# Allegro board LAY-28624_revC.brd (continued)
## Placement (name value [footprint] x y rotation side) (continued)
J56  JT4-1108HL  [CON_RJ45_XG_1X1_LED]  242.32 -1.52 0 top
J57  JMP1  [JMP_P254_T_1X1]  38.35 46.48 0 top
J58  CON_3PIN  [CON_WAFER_P254_S_1X3]  256.92 76.45 0 top
J59  CON_3PIN  [CON_WAFER_P254_S_1X3]  232.16 76.45 0 top
J60  HDR_1X3  [HDR_P254_M_T_1X3]  168.02 66.42 0 top
J61  JMP2  [JMP_P254_T_1X2]  55.88 90.68 0 top
L1  90ohm  [IND_CM_2012]  113.79 28.83 270 bottom
L2  90ohm  [IND_CM_2012]  116.33 28.83 270 bottom
L3  2.2uH  [IND_SWPA2520]  152.91 46.1 180 top
L4  2.2uH  [IND_SWPA2520]  130.68 46.74 180 top
L16  22uH  [IND_45X40]  59.69 130.43 90 top
L17  2.2uH  [IND_IHLP_2525]  189.61 78.23 180 top
L18  2.2uH  [IND_IHLP_2525]  209.93 136.91 180 top
L19  3.3uH  [IND_IHLP_2525]  31.5 112.14 0 top
L20  3.3uH  [IND_IHLP_2525]  31.5 101.35 0 top
L21  4.7uH  [IND_IHLP_2525]  68.96 80.39 0 top
L22  2.2uH  [IND_IHLP_2525]  31.5 90.55 0 top
L23  1.0uH  [IND_IHLP_4040]  115.95 104.52 0 top
L24  2.2uH  [IND_IHLP_2525]  210.19 53.21 270 top
L25  4.7uH  [IND_IHLP_2525]  263.14 53.21 270 top
M3  MH  [MH_580S340P]  261 189.58 180 top
M4  MH  [MH_580S340P]  237.18 189.58 0 top
M5  MH  [MH_580S340P]  261 213.78 180 top
M6  MH  [MH_580S340P]  237.18 213.78 0 top
M7  MH  [MH_580S340P]  207.8 189.58 180 top
M8  MH  [MH_580S340P]  231.95 189.58 180 top
M9  MH  [MH_580S340P]  231.95 213.78 180 top
M10  MH  [MH_580S340P]  207.8 213.78 180 top
M11  MH  [MH_580S340P]  31.56 189.58 0 top
M12  MH  [MH_580S340P]  31.56 213.78 0 top
M13  MH  [MH_580S340P]  7.74 189.58 0 top
M14  MH  [MH_580S340P]  7.74 213.78 0 top
M15  MH  [MH_580S340P]  36.79 189.58 0 top
M16  MH  [MH_580S340P]  36.79 213.78 0 top
M17  MH  [MH_580S340P]  60.94 189.58 0 top
M18  MH  [MH_580S340P]  60.94 213.78 0 top
NOREF  val  [unnamed]  166.12 114.05 90 top
NOREF#2  -  [#2]  -252.98 -202.18 0 top
Q1  IRLML6346  [SOT23]  169.29 91.69 90 bottom
Q2  IRLML6346  [SOT23]  165.23 91.69 270 bottom
Q3  IRLML6346  [SOT23]  102.36 35.94 90 top
Q4  IRLML6346  [SOT23]  97.66 35.94 90 top
Q11  IRFHM4226  [U8_FL]  37.97 99.82 90 top
Q12  IRF9321  [SO_8]  24.51 75.31 0 top
Q15  IRLML6346  [SOT23]  38.35 104.01 180 top
Q16  IRLML6346  [SOT23]  19.05 70.87 0 top
Q17  IRFHM4226  [U8_FL]  75.44 78.87 90 top
Q18  IRFH6200  [SO_8_FL]  39.24 89.15 90 top
Q20  IRLML6346  [SOT23]  75.82 83.06 180 top
Q21  IRLML6346  [SOT23]  38.23 94.36 180 top
Q27  IRLML6346  [SOT23]  54.86 125.6 0 top
Q28  IRLML6346  [SOT23]  54.86 129.67 0 top
Q29  IRLML2502  [SOT23]  54.86 133.73 0 top
Q30  MMBT4401  [SOT23]  9.53 67.82 0 top
Q31  IRFH6200  [SO_8_FL]  202.31 137.79 0 top
Q32  IRLML6346  [SOT23]  204.34 131.06 0 top
Q33  IRLML2030  [SOT23]  44.07 143.64 90 top
Q34  IRLML2030  [SOT23]  48.13 143.64 90 top
Q35  IRLML6346  [SOT23]  42.93 135.64 0 top
Q36  IRLML6346  [SOT23]  47.88 136.4 0 top
Q37  IRLML6346  [SOT23]  152.91 132.21 90 bottom
Q38  IRLML6346  [SOT23]  152.91 128.52 90 bottom
Q44  IRLML2030  [SOT23]  41.53 139.7 0 top
Q45  IRLML2030  [SOT23]  45.21 139.7 0 top
Q46  IRFH6200  [SO_8_FL]  129.03 112.78 270 bottom
Q47  IRLML6346  [SOT23]  129.03 112.4 270 top
Q48  IRLML2030  [SOT23]  104.9 150.37 180 bottom
Q49  IRLML6346  [SOT23]  105.03 146.43 90 bottom
Q50  MMBT3906  [SOT23]  34.92 38.1 180 bottom
R1  162  [0402]  169.42 125.6 180 bottom
R2  1K  [0402]  152.53 163.19 180 top
R3  162  [0402]  166.5 124.84 135 bottom
R4  10K  [0402]  162.43 163.7 270 top
R5  4.7K  [0402]  150.24 112.9 270 bottom
R6  4.7K  [0402]  73.32 113.73 90 bottom
R7  4.7K  [0402]  71.82 115.23 0 bottom
R9  4.7K  [0402]  59.01 115.83 90 bottom
R10  4.7K  [0402]  60.01 115.83 90 bottom
R11  4.7K  [0402]  61.01 115.83 90 bottom
R12  10  [0402]  153.42 115.57 180 bottom
R13  4.7K  [0402]  113.41 125.35 0 bottom
R14  33  [0402]  123.06 120.9 180 bottom
R15  33  [0402]  123.06 121.92 180 bottom
R16  33  [0402]  123.06 122.94 180 bottom
R17  4.7K  [0402]  72.77 142.75 270 bottom
R18  33  [0402]  121.03 123.57 180 bottom
R19  4.7K  [0402]  74.04 142.75 270 bottom
R20  33  [0402]  123.06 124.21 180 bottom
R21  4.7K  [0402]  75.31 142.75 270 bottom
R22  33  [0402]  121.03 124.84 180 bottom
R23  4.7K  [0402]  76.58 142.75 270 bottom
R24  33  [0402]  123.06 125.48 180 bottom
R25  4.7K  [0402]  77.85 142.75 270 bottom
R26  33  [0402]  121.03 126.11 180 bottom
R27  4.7K  [0402]  79.12 142.75 270 bottom
R28  33  [0402]  123.06 126.75 180 bottom
R29  4.7K  [0402]  80.39 142.75 270 bottom
R30  33  [0402]  123.06 127.76 180 bottom
R31  4.7K  [0402]  81.66 142.75 270 bottom
R32  33  [0402]  123.06 128.78 180 bottom
R33  4.7K  [0402]  85.47 142.75 270 bottom
R34  4.7K  [0402]  86.74 142.75 270 bottom
R35  4.7K  [0402]  88.01 142.75 270 bottom
R36  4.7K  [0402]  89.28 142.75 270 bottom
R37  4.7K  [0402]  90.55 142.75 270 bottom
R38  4.7K  [0402]  93.09 142.75 270 bottom
R39  4.7K  [0402]  91.82 142.75 270 bottom
R40  4.7K  [0402]  94.36 142.75 270 bottom
R41  4.7K  [0402]  118.75 129.41 180 bottom
R42  4.7K  [0402]  104.27 124.21 0 bottom
R43  4.7K  [0402]  102.11 134.49 90 bottom
R44  4.7K  [0402]  118.75 130.43 180 bottom
R47  4.7K  [0402]  118.75 128.4 180 bottom
R54  4.7K  [0402]  254.63 131.95 90 top
R55  4.7K  [0402]  270.51 138.05 270 top
R56  4.7K  [0402]  255.14 133.73 180 top
R57  4.7K  [0402]  269.62 133.6 90 top
R58  33  [0402]  255.65 131.95 90 top
R59  10  [0402]  164.47 99.06 270 bottom
R60  10K  [0402]  155.45 94.74 90 bottom
R61  0  [0402]  163.19 102.36 270 bottom
R62  10K  [0402]  154.43 94.74 90 bottom
R63  10K  [0402]  160.53 94.74 90 bottom
R64  10K  [0402]  159.51 94.74 90 bottom
R65  10K  [0402]  153.42 94.74 90 bottom
R66  10K  [0402]  157.48 94.74 90 bottom
R67  10K  [0402]  158.5 94.74 90 bottom
R68  10K  [0402]  156.46 94.74 90 bottom
R69  4.7K  [0402]  71.63 109.6 0 bottom
R70  4.7K  [0402]  150.24 106.68 0 bottom
R71  4.7K  [0402]  173.1 101.6 270 bottom
R72  4.7K  [0402]  173.1 98.93 90 bottom
R73  4.7K  [0402]  164.21 102.36 270 bottom
R74  4.7K  [0402]  167.51 101.85 180 bottom
R81  4.7K  [0402]  74.04 105.16 0 bottom
R82  4.7K  [0402]  153.42 116.59 180 bottom
R83  1K  [0402]  73.52 111.13 90 bottom
R84  1K  [0402]  153.29 105.41 180 bottom
R85  4.7K  [0402]  70.32 103.42 180 bottom
R86  4.7K  [0402]  170.05 98.93 270 bottom
R87  4.7K  [0402]  169.04 98.93 270 bottom
R88  4.7K  [0402]  241.68 148.72 0 top
R89  4.7K  [0402]  241.68 149.86 0 top
R90  4.7K  [0402]  240.03 145.92 180 top
R91  4.7K  [0402]  240.03 146.94 180 top
R94  4.7K  [0402]  72.02 111.63 180 bottom
R95  4.7K  [0402]  171.07 98.93 270 bottom
R96  4.7K  [0402]  72.02 110.63 180 bottom
R97  4.7K  [0402]  172.08 98.93 270 bottom
R98  4.7K  [0402]  70.32 104.42 0 bottom
R99  4.7K  [0402]  257.56 154.94 270 top
R101  4.7K  [0402]  77.22 98.68 0 top
R102  4.7K  [0402]  68.96 137.41 0 top
R103  510  [0402]  71.63 94.36 270 top
R104  698  [0402]  153.42 118.62 0 bottom
R105  698  [0402]  153.42 117.6 0 bottom
R106  10K  [0402]  136.4 128.02 0 bottom
R107  10K  [0402]  20.07 153.42 180 top
R108  10  [0402]  20.07 141.99 0 top
R109  10K  [0402]  20.07 139.45 0 top
R110  10K  [0402]  20.07 150.88 180 top
R111  10K  [0402]  20.07 140.72 180 top
R112  10K  [0402]  20.07 143.26 180 top
R113  10K  [0402]  20.07 145.8 180 top
R114  10K  [0402]  20.07 148.34 180 top
R115  10  [0402]  175.13 101.6 90 bottom
R116  10  [0402]  176.15 101.6 90 bottom
R117  10  [0402]  179.32 106.3 0 bottom
R118  10  [0402]  181.36 106.81 0 bottom
R119  10  [0402]  174.12 101.6 90 bottom
R120  10  [0402]  181.36 105.79 0 bottom
R121  10  [0402]  174.12 99.19 90 bottom
R122  10  [0402]  179.32 105.28 0 bottom
R123  4.7K  [0402]  178.56 103.51 0 bottom
R124  4.7K  [0402]  179.32 108.97 180 bottom
R125  10  [0402]  179.2 101.98 90 bottom
R126  10  [0402]  181.36 108.97 0 bottom
R127  10  [0402]  177.67 101.35 0 bottom
R128  10  [0402]  181.36 107.82 0 bottom
R129  10  [0402]  181.36 104.78 180 bottom
R130  10  [0402]  165.99 102.36 270 bottom
R131  1.5K  [0402]  146.43 56.01 90 top
R132  4.7K  [0402]  146.43 58.8 90 top
R133  330  [0402]  182.01 50.01 0 bottom
R134  180  [0402]  182.01 48.01 0 bottom
R138  1K  [0402]  150.5 60.71 0 top
R139  200  [0402]  172.52 111.24 270 bottom
R140  698  [0402]  172.53 113.92 180 bottom
R155  10K  [0402]  97.02 38.35 0 top
R156  10K  [0402]  101.72 38.48 0 top
R157  0  [0402]  101.72 33.53 0 top
R158  100K  [0402]  100.2 34.04 90 top
R159  100K  [0402]  104.01 33.53 0 top
R160  0  [0402]  98.67 33.53 0 top
R161  1K  [0402]  97.15 33.02 270 top
R162  1K  [0402]  104.52 31.88 270 top
R163  51.1K  [0402]  97.15 26.03 90 top
R164  51.1K  [0402]  106.93 28.19 270 top
R165  18.2K  [0402]  96.13 26.03 270 top
R166  18.2K  [0402]  107.44 29.84 180 top
R167  0  [0402]  114.29 28.83 270 bottom
R168  0  [0402]  113.28 28.83 270 bottom
R169  0  [0402]  116.83 28.83 270 bottom
R170  0  [0402]  115.82 28.83 270 bottom
R171  10K  [0402]  155.32 101.35 0 bottom
R172  49.9  [0402]  155.32 99.31 0 bottom
R173  49.9  [0402]  154.3 102.36 0 bottom
R175  33  [0402]  89.79 89.54 0 top
R176  1K  [0402]  89.79 88.52 0 top
R177  330  [0402]  60.45 147.45 180 top
R178  330  [0402]  60.45 146.05 180 top
R179  330  [0402]  59.94 151.13 90 top
R188  5.1  [0402]  153.16 109.35 0 bottom
R189  0.33  [0402]  190.88 124.08 0 bottom
R190  0  [0402]  190.88 125.09 0 bottom
R192  0.33  [0402]  190.88 127.89 0 bottom
R193  0  [0402]  190.88 128.91 0 bottom
R194  5.1  [0402]  151.76 105.92 90 bottom
R195  5.1  [0402]  149.35 118.11 90 bottom
R196  100  [0402]  132.59 67.31 270 top
R197  100  [0402]  132.59 65.28 270 top
R198  100  [0402]  137.92 61.09 270 top
R199  100  [0402]  138.94 61.09 270 top
R200  100  [0402]  125.48 67.18 270 top
R201  100  [0402]  125.48 65.15 270 top
R202  100  [0402]  130.81 61.09 270 top
R203  100  [0402]  131.83 61.09 270 top
R204  4.7K  [0402]  58.67 125.48 180 top
R205  100  [0402]  150.37 121.03 180 bottom
R206  100  [0402]  150.37 120.02 180 bottom
R207  75  [0603]  155.7 29.84 180 bottom
R208  75  [0603]  158.75 29.84 180 bottom
R209  33  [0402]  164.08 46.48 180 top
R210  75  [0603]  161.8 29.84 180 bottom
R211  33  [0402]  166.12 50.55 180 top
R212  75  [0603]  164.85 29.84 180 bottom
R213  33  [0402]  164.08 47.5 180 top
R214  33  [0402]  164.08 48.51 180 top
R215  33  [0402]  164.08 49.53 180 top
R216  33  [0402]  164.08 45.47 180 top
R217  33  [0402]  151.38 48.01 180 top
R218  510  [0402]  154.69 56.13 0 top
R219  510  [0402]  152.65 56.13 180 top
R220  100  [0402]  160.02 56.13 270 top
R221  0  [0402]  166.12 51.56 0 top
R222  0  [0402]  156.72 55.63 90 top
R224  15  [0402]  153.42 46.61 180 bottom
R227  2.49K  [0402]  152.91 52.58 270 top
R228  4.7K  [0402]  166.12 46.48 0 top
R229  4.7K  [0402]  166.12 47.5 0 top
R230  4.7K  [0402]  166.12 48.51 0 top
R231  4.7K  [0402]  166.12 49.53 0 top
R232  4.7K  [0402]  166.12 45.47 0 top
R233  4.7K  [0402]  154.69 55.12 0 top
R234  4.7K  [0402]  152.65 55.12 180 top
R235  4.7K  [0402]  157.73 55.63 90 top
R236  75  [0603]  139.83 29.84 180 bottom
R237  75  [0603]  142.88 29.84 180 bottom
R238  33  [0402]  143.89 51.18 180 top
R239  33  [0402]  141.86 47.12 180 top
R240  75  [0603]  145.92 29.84 180 bottom
R241  75  [0603]  148.97 29.84 180 bottom
R242  33  [0402]  141.86 48.13 180 top
R243  33  [0402]  141.86 49.15 180 top
R244  33  [0402]  141.86 50.16 180 top
R245  33  [0402]  141.86 46.1 180 top
R246  33  [0402]  129.16 48.64 180 top
R247  510  [0402]  132.46 56.77 0 top
R248  510  [0402]  130.43 56.77 180 top
R249  100  [0402]  137.79 56.77 270 top
R250  0  [0402]  142.37 53.47 90 top
R251  0  [0402]  134.49 56.26 90 top
R252  4.7K  [0402]  136.78 56.77 90 top
R253  15  [0402]  131.19 47.24 180 bottom
R256  2.49K  [0402]  130.68 53.21 270 top
R257  4.7K  [0402]  143.89 47.12 0 top
R258  4.7K  [0402]  143.89 48.13 0 top
R259  4.7K  [0402]  143.89 49.15 0 top
R260  4.7K  [0402]  143.89 50.16 0 top
R261  4.7K  [0402]  143.89 46.1 0 top
R262  4.7K  [0402]  132.46 55.75 0 top
R263  4.7K  [0402]  130.43 55.75 180 top
R264  4.7K  [0402]  135.51 56.26 90 top
R398  4.7K  [0402]  255.52 154.94 90 top
R399  4.7K  [0402]  177.42 211.58 270 top
R400  4.7K  [0402]  267.21 93.6 180 top
R401  4.7K  [0402]  267.21 85.85 180 top
R402  4.7K  [0402]  267.21 86.87 180 top
R403  4.7K  [0402]  267.21 87.88 180 top
R404  4.7K  [0402]  256.54 154.94 90 top
R405  4.7K  [0402]  267.21 96.01 180 top
R406  4.7K  [0402]  256.16 144.4 270 top
R407  4.7K  [0402]  255.14 144.4 270 top
R408  4.7K  [0402]  267.21 94.62 180 top
R409  4.7K  [0402]  253.87 154.43 180 top
R410  4.7K  [0402]  253.87 155.45 180 top
R411  4.7K  [0402]  91.31 191.77 90 top
R494  1K  [0402]  48.89 110.87 270 top
R495  33  [0402]  52.7 113.79 0 top
R496  4.7K  [0402]  19.18 124.46 90 top
R497  10K  [0402]  11.3 127.76 0 top
R498  10K  [0402]  7.24 127.76 180 top
R499  4.7K  [0402]  98.17 142.75 270 bottom
R500  4.7K  [0402]  99.44 142.75 270 bottom
R501  4.7K  [0402]  100.71 142.75 270 bottom
R502  10K  [0402]  101.98 137.79 270 bottom
R503  1K  [0402]  101.98 142.75 270 bottom
R504  10K  [0402]  103.25 137.79 270 bottom
R505  1K  [0402]  103.25 142.75 270 bottom
R506  10K  [0402]  104.52 137.79 270 bottom
R507  1K  [0402]  104.52 142.75 270 bottom
R508  10K  [0402]  105.79 137.79 270 bottom
R509  1K  [0402]  105.79 142.75 270 bottom
R511  33  [0402]  89.79 99.95 0 top
R513  1K  [0402]  89.79 100.97 0 top
R517  33  [0402]  89.79 108.2 0 top
R518  1K  [0402]  89.79 109.22 0 top
R519  49.9  [0402]  243.33 135.89 0 top
R520  0  [0402]  241.3 135.89 0 top
R521  0  [0402]  241.3 137.16 0 top
R523  49.9  [0402]  243.33 137.16 0 top
R524  49.9  [0402]  238.38 143.64 270 top
R525  0  [0402]  238.38 141.6 90 top
R526  0  [0402]  237.11 141.6 90 top
R527  49.9  [0402]  235.97 143.64 90 top
R528  49.9  [0402]  237.11 143.64 270 top
R530  0  [0402]  235.97 141.6 90 top
R532  0  [0402]  234.7 141.6 90 top
R534  49.9  [0402]  234.7 143.64 90 top
R535  49.9  [0402]  229.87 138.81 0 top
R536  0  [0402]  231.9 138.81 180 top
R537  0  [0402]  231.9 137.54 180 top
R538  49.9  [0402]  229.87 137.54 0 top
R541  150  [0402]  157.61 68.33 180 top
R542  150  [0402]  157.61 69.98 180 top
R543  150  [0402]  153.67 73.03 180 top
R544  150  [0402]  153.67 74.55 180 top
R549  10  [0402]  146.94 62.99 0 top
R656  1K  [0402]  42.29 100.84 180 top
R659  0  [0402]  40.77 101.35 90 top
R662  10K  [0402]  42.8 102.36 270 top
R663  10K  [0402]  19.05 73.91 270 top
R666  1K  [0402]  41.78 104.65 90 top
R669  10K  [0402]  40.77 104.65 90 top
R670  1K  [0402]  15.62 70.23 270 top
R671  10K  [0402]  16.64 70.23 270 top
R672  1K  [0402]  79.76 79.88 180 top
R673  1K  [0402]  44.45 91.57 270 top
R675  0  [0402]  78.23 80.39 90 top
R676  0  [0402]  43.43 91.57 90 top
R678  10K  [0402]  80.26 81.41 270 top
R679  10K  [0402]  42.8 93.98 270 top
R681  1K  [0402]  79.25 83.69 90 top
R682  1K  [0402]  42.29 95.5 180 top
R684  10K  [0402]  78.23 83.69 90 top
R685  10K  [0402]  40.77 95 90 top
R694  10  [0402]  224.03 149.61 180 top
R695  1K  [0402]  229.62 149.61 180 top
R696  1K  [0402]  231.14 148.08 90 top
R697  100K  [0402]  228.35 143.64 0 top
R699  510  [0402]  24.26 10.03 0 top
R700  0  [1206]  220.73 241.05 0 top
R701  0  [1206]  64.26 137.79 0 top
R702  510  [0402]  29.59 10.03 180 top
R703  10K  [0402]  52.32 129.03 90 top
R704  10K  [0402]  52.32 131.06 270 top
R705  4.7K  [0402]  18.67 62.74 0 top
R706  4.7K  [0402]  11.3 70.23 270 top
R707  100  [0402]  18.67 60.71 180 top
R708  4.7K  [0402]  19.05 68.07 180 top
R709  3.74K  [0402]  12.32 70.23 90 top
R710  4.7K  [0402]  7.11 68.07 270 top
R711  100  [0402]  15.75 60.71 180 top
R712  4.7K  [0402]  13.34 70.23 270 top
R713  1K  [0402]  7.62 64.9 180 top
R714  100K  [0402]  15.75 61.72 180 top
R715  100K  [0402]  8.13 63.37 90 top
R728  169K  [0402]  219.46 132.97 90 top
R729  10K  [0402]  201.8 76.84 0 top
R730  107K  [0402]  199.14 74.3 90 top
R731  10K  [0402]  222.12 135.51 0 top
R732  10K  [0402]  200.15 74.3 90 top
R733  1.65K  [0402]  203.83 77.34 90 top
R734  10K  [0402]  220.47 132.97 90 top
R735  2.05K  [0402]  224.16 136.02 90 top
R736  10K  [0402]  222.12 138.56 0 top
R737  10K  [0402]  201.8 77.85 180 top
R738  10K  [0402]  201.8 79.88 0 top
R739  10K  [0402]  222.12 136.52 180 top
R740  10K  [0402]  201.8 75.82 180 top
R741  10K  [0402]  222.12 134.49 180 top
R742  0  [0402]  199.9 76.71 0 bottom
R743  0  [0402]  220.22 135.38 0 bottom
R744  14.3K  [0402]  199.9 77.72 0 bottom
R745  5.9K  [0402]  220.22 136.4 0 bottom
R746  187K  [0402]  21.97 116.08 270 top
R747  226K  [0402]  21.97 105.28 270 top
R748  10K  [0402]  19.3 113.54 180 top
R749  10K  [0402]  19.3 102.74 180 top
R750  10K  [0402]  20.95 116.08 270 top
R751  2.21K  [0402]  17.27 113.03 270 top
R752  10K  [0402]  19.3 112.52 0 top
R753  10K  [0402]  19.3 110.49 180 top
R754  10K  [0402]  20.95 105.28 270 top
R755  2.43K  [0402]  17.27 102.23 270 top
R756  10K  [0402]  19.3 101.73 0 top
R757  10K  [0402]  19.3 99.7 180 top
R758  10K  [0402]  19.3 114.55 0 top
R759  10K  [0402]  19.3 103.76 0 top
R760  0  [0402]  21.21 113.67 180 bottom
R761  0  [0402]  21.21 102.87 180 bottom
R762  4.99K  [0402]  21.21 112.65 180 bottom
R763  3.83K  [0402]  21.21 101.85 180 bottom
R764  309K  [0402]  59.44 84.33 270 top
R765  412K  [0402]  21.97 94.49 270 top
R766  10K  [0402]  56.77 81.79 180 top
R767  10K  [0402]  19.3 91.95 180 top
R768  10K  [0402]  58.42 84.33 270 top
R769  2.55K  [0402]  54.74 81.28 270 top
R770  10K  [0402]  20.95 94.49 270 top
R771  10K  [0402]  18.8 89.41 90 bottom
R772  10K  [0402]  19.3 88.9 180 top
R773  10K  [0402]  56.77 80.77 0 top
R774  10K  [0402]  56.77 78.74 180 top
R775  2.32K  [0402]  17.27 91.44 270 top
R776  10K  [0402]  56.77 82.8 0 top
R777  10K  [0402]  19.3 92.96 0 top
R778  0  [0402]  58.67 81.92 180 bottom
R779  0  [0402]  21.21 92.08 180 bottom
R780  2.49K  [0402]  58.67 80.9 180 bottom
R781  1.78K  [0402]  21.21 91.06 180 bottom
R782  1K  [0402]  200.41 132.72 180 top
R783  0  [0402]  202.44 132.72 180 top
R784  10K  [0402]  200.91 131.19 90 top
R785  1K  [0402]  203.45 128.52 180 top
R786  10K  [0402]  201.93 129.03 270 top
R797  20K  [0402]  90.55 137.79 270 bottom
R798  20K  [0402]  91.82 137.79 270 bottom
R799  20K  [0402]  88.01 137.79 270 bottom
R800  20K  [0402]  89.28 137.79 270 bottom
R801  20K  [0402]  94.36 137.79 90 bottom
R802  20K  [0402]  100.71 137.79 90 bottom
R803  20K  [0402]  99.44 137.79 90 bottom
R804  20K  [0402]  98.17 137.79 90 bottom
R806  4.32K  [0402]  203.45 126.49 180 top
R807  10K  [0402]  203.45 127.51 0 top
R813  4.7K  [0402]  70.32 105.43 180 bottom
R814  49.9  [0402]  153.8 100.84 270 bottom
R815  1K  [0402]  51.69 141.1 180 top
R816  0  [0402]  45.34 134.37 270 top
R817  0  [0402]  48.89 133.86 0 top
R818  10K  [0402]  45.85 131.83 180 top
R819  10K  [0402]  47.88 131.83 180 top
R820  1K  [0402]  43.81 131.83 180 top
R821  10K  [0402]  43.81 132.84 180 top
R822  0  [0402]  153.92 52.58 270 top
R823  4.7K  [0402]  159 56.13 90 top
R824  0  [0402]  154.43 52.7 270 bottom
R825  0  [0402]  131.7 53.21 270 top
R826  0  [0402]  132.21 53.34 270 bottom
R829  1K  [0402]  231.9 132.97 0 top
R830  1K  [0402]  149.86 127.51 0 bottom
R831  10K  [0402]  150.37 129.03 270 bottom
R834  1K  [0402]  238.25 132.08 90 top
R835  49.9  [0402]  229.87 136.4 180 top
R836  0  [0402]  231.9 136.4 180 top
R837  0  [0402]  231.9 135.13 180 top
R838  49.9  [0402]  229.87 135.13 180 top
R839  10  [0402]  235.46 130.94 0 bottom
R841  10  [0402]  238.12 139.45 180 bottom
R842  1K  [0402]  231.9 131.95 0 top
R843  1K  [0402]  241.3 134.75 180 top
R844  1K  [0402]  231.9 133.98 0 top
R849  4.7K  [0402]  265.18 149.61 0 top
R850  4.7K  [0402]  265.18 148.59 0 top
R851  4.7K  [0402]  265.18 147.57 0 top
R852  4.7K  [0402]  265.18 146.56 0 top
R853  4.7K  [0402]  144.53 122.94 0 bottom
R861  0  [1206]  246.13 241.05 0 top
R862  0  [1206]  233.43 241.05 0 top
R863  0  [1206]  258.83 241.05 0 top
R864  20K  [0402]  113.41 126.37 0 bottom
R865  51  [0402]  269.49 140.59 90 top
R866  51  [0402]  269.49 138.05 90 top
R867  51  [0402]  270.51 140.59 270 top
R868  33  [0402]  274.57 138.05 270 top
R869  51  [0402]  273.56 138.05 270 top
R870  4.7K  [0402]  24 71.88 0 top
R871  4.7K  [0402]  272.54 138.05 270 top
R872  4.7K  [0402]  271.53 138.05 270 top
R873  0  [0402]  149.22 113.92 270 bottom
R874  0  [0402]  149.73 105.16 90 bottom
R875  4.7K  [0402]  172.08 101.6 90 bottom
R876  4.7K  [0402]  150.75 103.12 90 bottom
R877  4.7K  [0402]  153.29 103.38 180 bottom
R878  4.7K  [0402]  153.29 104.39 180 bottom
R879  4.7K  [0402]  153.29 106.43 180 bottom
R880  0  [0402]  150.75 114.43 180 bottom
R881  4.7K  [0402]  171.07 101.6 90 bottom
R882  0  [0402]  149.73 103.12 90 bottom
R883  1K  [0402]  103.76 89.28 0 top
R884  4.7K  [0402]  180.01 49.01 180 bottom
R885  0  [0402]  182.01 49.01 180 bottom
R886  4.7K  [0402]  183.51 51.51 90 bottom
R887  0  [0402]  197.02 44 180 bottom
R888  0  [0402]  185.51 48.51 270 bottom
R889  0  [0402]  186.01 47.01 0 bottom
R890  0  [0402]  184.51 47.51 90 bottom
R891  0  [0402]  185.01 46 0 bottom
R892  0  [0402]  184.01 45 0 bottom
R895  4.7K  [0402]  197.52 45.5 90 bottom
R896  100  [0402]  197.52 47.51 270 bottom
R897  4.7K  [0402]  198.52 46.5 90 bottom
R898  0  [0402]  178.94 45.09 0 top
R899  0  [0402]  187.51 45.5 90 bottom
R900  0  [0402]  184.01 44 0 bottom
R901  2.00K  [0402]  190.01 40 0 bottom
R902  100  [0402]  193.29 8.38 90 bottom
R903  100  [0402]  189.74 8.38 90 bottom
R904  124K  [0402]  103.25 108.46 270 top
R905  1.65K  [0402]  98.55 105.41 270 top
R906  10K  [0402]  102.23 108.46 270 top
R907  10K  [0402]  100.58 105.92 180 top
R908  10K  [0402]  100.58 104.9 0 top
R909  1K  [0402]  131.57 114.43 90 top
R910  10K  [0402]  100.58 106.93 0 top
R911  0  [0402]  102.49 106.05 180 bottom
R912  0  [0402]  131.57 111.89 270 top
R913  10K  [0402]  102.49 105.03 180 bottom
R914  10K  [0402]  101.09 102.36 90 top
R915  200  [0402]  99.57 101.85 180 top
R916  10K  [0402]  127.76 114.94 180 top
R917  60.4  [0402]  102.36 99.7 90 top
R918  0  [0402]  101.22 97.28 180 top
R919  1K  [0402]  125.48 112.4 90 top
R920  10K  [0402]  126.49 112.4 90 top
R921  261K  [0402]  267.08 62.74 180 top
R922  10K  [0402]  211.58 65.4 90 top
R923  150K  [0402]  214.12 62.73 180 top
R924  10K  [0402]  264.54 65.41 90 top
R925  10K  [0402]  214.12 63.75 180 top
R926  1.87K  [0402]  211.07 67.43 180 top
R927  10K  [0402]  267.08 63.75 180 top
R928  2.49K  [0402]  264.03 67.44 180 top
R929  10K  [0402]  261.49 65.41 90 top
R930  14K  [0402]  208.53 65.4 90 top
R931  10K  [0402]  210.57 65.4 270 top
R932  10K  [0402]  263.53 65.41 270 top
R933  10K  [0402]  212.6 65.4 270 top
R934  10K  [0402]  265.56 65.41 270 top
R935  0  [0402]  211.71 63.49 90 bottom
R936  0  [0402]  264.67 63.5 90 bottom
R937  10K  [0402]  210.69 63.49 90 bottom
R938  3.09K  [0402]  263.65 63.5 90 bottom
R939  5.1  [0402]  153.16 111.89 0 bottom
R940  4.7K  [0402]  109.09 87.76 90 top
R941  4.7K  [0402]  177.8 49.02 180 top
R942  4.7K  [0402]  178.82 56.77 90 top
R943  4.7K  [0402]  207.26 46.48 0 top
R945  1M  [0402]  102.36 149.73 270 bottom
R946  0  [0402]  107.57 148.72 270 bottom
R947  10K  [0402]  107.57 145.67 90 bottom
R948  1K  [0402]  101.85 145.29 0 bottom
R949  10K  [0402]  102.36 146.81 270 bottom
R950  1K  [0402]  186.01 51.01 180 bottom
R951  26.7K  [0402]  100.71 32.51 0 top
R952  4.7K  [0402]  96.65 132.97 0 bottom
R953  1K  [0402]  96.65 131.95 0 bottom
R954  1K  [0402]  37.85 36.83 180 bottom
R955  4.7K  [0402]  37.85 37.85 180 bottom
R957  4.7K  [0402]  230.81 49.01 180 bottom
R958  4.7K  [0402]  234.31 51.51 90 bottom
R959  0  [0402]  232.81 49.01 180 bottom
R960  0  [0402]  247.82 44 180 bottom
R961  0  [0402]  236.31 48.51 270 bottom
R962  0  [0402]  236.81 47.01 0 bottom
R963  0  [0402]  235.31 47.51 90 bottom
R964  0  [0402]  235.81 46 0 bottom
R965  4.7K  [0402]  229.62 56.77 90 top
R966  4.7K  [0402]  228.6 49.02 180 top
R967  0  [0402]  234.81 45 0 bottom
R968  4.7K  [0402]  248.32 45.5 90 bottom
R969  100  [0402]  248.32 47.51 270 bottom
R970  4.7K  [0402]  249.32 46.5 90 bottom
R971  0  [0402]  229.74 45.09 0 top
R972  0  [0402]  238.31 45.5 90 bottom
R973  0  [0402]  234.81 44 0 bottom
R974  2.00K  [0402]  240.81 40 0 bottom
R975  1K  [0402]  236.81 51.01 180 bottom
R976  4.7K  [0402]  257.94 46.48 0 top
R977  100  [0402]  244.09 8.38 90 bottom
R978  100  [0402]  240.54 8.38 90 bottom
R979  4.7K  [0402]  231.27 99.19 0 top
R980  0.001  [RES_WSL2726]  121.41 94.74 270 top
R981  10  [0402]  116.08 95.25 0 top
R982  10  [0402]  116.08 94.23 0 top
R983  0  [0402]  110.62 96.27 180 bottom
R984  0  [0402]  110.62 97.28 180 bottom
R985  0  [0402]  109.73 98.17 180 top
R986  0  [1206]  258.44 80.9 180 top
R987  0  [1206]  233.68 80.9 180 top
R988  82  [0402]  256.92 114.3 90 top
R989  82  [0402]  226.95 126.49 180 top
R990  82  [0402]  256.92 116.33 270 top
R991  82  [0402]  224.92 126.49 0 top
R992  82  [0402]  262.51 119.76 180 top
R993  150  [0402]  257.43 111.51 180 top
R994  82  [0402]  225.42 123.06 270 top
R995  150  [0402]  237.74 123.19 0 top
R996  82  [0402]  260.48 119.76 0 top
R997  150  [0402]  257.43 112.78 180 top
R998  82  [0402]  225.42 121.03 90 top
R999  150  [0402]  237.74 124.46 0 top
R1000  150  [0402]  261.37 108.59 270 top
R1001  150  [0402]  237.74 122.17 0 top
R1002  150  [0402]  260.35 108.59 270 top
R1003  150  [0402]  237.74 121.16 0 top
R1004  130  [0402]  260.48 118.75 0 top
R1005  130  [0402]  226.44 121.03 90 top
R1006  130  [0402]  262.51 118.75 180 top
R1007  130  [0402]  226.44 123.06 270 top
R1008  130  [0402]  257.94 116.33 270 top
R1009  130  [0402]  224.92 125.48 0 top
R1010  130  [0402]  257.94 114.3 90 top
R1011  130  [0402]  226.95 125.48 180 top
R1012  0  [0402]  241.3 139.57 0 top
R1013  49.9  [0402]  243.33 139.57 0 top
R1014  49.9  [0402]  243.33 138.3 180 top
R1015  0  [0402]  241.3 138.3 0 top
R1016  10K  [0402]  65.15 97.66 270 bottom
SW1  SWITCH_DIP_8  [CON_SWITCH_X8]  77.22 141.35 90 top
SW2  SWITCH_DIP_8  [CON_SWITCH_X8]  89.92 141.35 90 top
SW3  SWITCH_DIP_8  [CON_SWITCH_X8]  102.62 141.35 90 top
SW4  SWITCH  [CON_SW_60X60_2P2_34]  16.52 2.52 0 top
SW5  SWITCH  [CON_SW_60X60_2P2_34]  7.02 2.52 0 top
T1  GST5009LF  [MAG_GST5009]  160.02 34.54 180 top
T2  GST5009LF  [MAG_GST5009]  144.14 34.54 180 top
TP1  -  [TP]  127 85.85 0 top
TP2  -  [TP]  135.25 130.81 0 top
TP11  -  [TP]  197.1 120.52 0 top
TP12  -  [TP]  198.88 120.52 0 top
TP13  -  [TP]  197.1 122.94 0 top
TP14  -  [TP]  198.88 122.94 0 top
TP15  -  [TP]  133.73 87.5 180 bottom
TP16  -  [TP]  133.73 86.36 180 bottom
TP17  -  [TP]  135.76 85.85 180 bottom
TP18  -  [TP]  135.76 84.71 180 bottom
U1  T1024  [BGA_P080_780]  166.12 114.05 90 top
U2  74LVC16373  [TSSOP_48W]  129.29 126.75 0 bottom
U4  JS28F00AM29EWHA  [TSOP1_56]  112.14 128.65 180 top
U8  74LVC1G86  [SC70_5]  110.49 119.89 90 top
U9  74LVC1G86  [SC70_5]  103.38 119.89 90 top
U10  74LVC1G86  [SC70_5]  106.93 119.89 90 top
U13  MT25QL512ABA1ESF-0SIT  [SO_16L]  262.64 136.91 0 top
U15  N25Q512A13GF840F  [WSON_8]  262.64 136.91 90 top
U19  PCA9546APW  [TSSOP_16]  256.29 149.61 270 top
U20  TXBN0304RSV  [QFN_P040_D040_B260X180_16]  68.58 143.13 0 top
U21  FXLP34P5X  [SC70_5]  76.71 99.57 180 bottom
U22  FXLP34P5X  [SC70_5]  68.58 139.45 90 top
U23  74LVC1G66  [SC70_5]  148.72 58.67 270 top
U24  74LVC1G66  [SC70_5]  148.72 55.88 270 top
U37  MAX1558H  [DFN_P050_D040_B300_10_E230X150]  101.34 28.19 270 top
U38  VBUS054B-HSF  [TVS_LLP75_6L]  115.06 26.54 180 top
U39  MAX3232  [TSSOP_16]  136.14 66.42 90 top
U41  MAX3232  [TSSOP_16]  129.03 66.42 90 top
U43  LCDA15C-8  [SO_16]  131.19 33.4 0 top
U44  AT24C256  [SO_8]  236.47 150.5 0 top
U45  ADT7461  [MSOP_8]  144.91 120.52 180 bottom
U46  RTL8211E-VB  [QFN_P040_D040_B600_48_E440]  158.5 49.91 90 top
U47  SRV05-4  [SOT23_6]  155.96 42.29 270 top
U48  SRV05-4  [SOT23_6]  162.05 42.29 270 top
U49  RTL8211E-VB  [QFN_P040_D040_B600_48_E440]  136.27 50.55 90 top
U50  SRV05-4  [SOT23_6]  139.57 42.29 270 top
U51  SRV05-4  [SOT23_6]  145.54 42.29 270 top
U65  EPM570GF256  [BGA_P100_256]  64.52 106.43 0 top
U68  ICS843002-01  [TSSOP_20]  152.27 67.18 0 top
U81  TPS51200  [DFN_P050_D040_B300_10_E240X165]  227.33 146.69 270 top
U83  MIC811  [SOT143]  19.05 65.41 180 top
U84  74LVC2G74  [U8]  11.18 64.01 180 top
U85  74AHC1G14  [SC70_5]  12.32 61.21 90 top
U86  IR3473  [QFN_SUPIRBUCK_4X5]  197.23 78.23 90 top
U87  IR3475  [QFN_SUPIRBUCK_4X5]  217.55 136.91 90 top
U88  IR3473  [QFN_SUPIRBUCK_4X5]  23.88 112.14 270 top
U89  IR3473  [QFN_SUPIRBUCK_4X5]  23.88 101.35 270 top
U90  IR3475  [QFN_SUPIRBUCK_4X5]  23.88 90.55 270 top
U91  IR3473  [QFN_SUPIRBUCK_4X5]  61.34 80.39 270 top
U93  RClamp0524J.TCT  [TVS_SLP2710P8]  44.45 37.34 180 bottom
U94  RClamp0524J.TCT  [TVS_SLP2710P8]  30.73 37.34 180 bottom
U95  MIC47100YMME  [MSOP_8_E170]  207.9 125.98 180 top
U97  IDT9FGV0641  [QFN_P040_D040_B500_40_E370]  236.6 136.91 90 top
U100  DS1339U-33+  [MSOP_8]  105.03 86.61 0 top
U101  AQR105  [BGA_P100_324]  191.52 48.01 180 top
U102  MX25V4006E  [SO_8]  208.28 43.05 0 top
U103  IR3475  [QFN_SUPIRBUCK_4X5]  105.16 104.52 270 top
U104  74CBTLV1G125  [SC70_5]  100.46 99.57 0 top
U105  IR3473  [QFN_SUPIRBUCK_4X5]  210.19 60.83 180 top
U106  IR3473  [QFN_SUPIRBUCK_4X5]  263.14 60.83 180 top
U107  MT29F8G08ABBCAH4:C  [BGA_P080_NAND_63]  93.73 128.02 0 top
U108  AQR105  [BGA_P100_324]  242.32 48.01 180 top
U109  MX25V4006E  [SO_8]  259.08 43.05 0 top
U110  PI3PCIE3212  [QFN_P050_D040_B450X250_20_E3X1]  234.7 101.35 0 top
U111  INA220A  [MSOP_10]  109.73 95.63 0 top
U112  ICS859S0212I  [TSSOP_16]  232.16 122.94 0 top
U113  ICS859S0212I  [TSSOP_16]  261.49 113.92 270 top
X1  24MHz,+/-50ppm  [OSC_7X5_4]  84.84 89.28 0 top
X2  32.768KHz  [OSC_32X25_4]  51.69 111.38 0 top
X3  100MHz,+/-50ppm  [OSC_7X5_4]  84.84 97.54 0 top
X5  66.66MHz,+/-50ppm  [OSC_7X5_4]  84.84 105.79 0 top
Y1  25MHz  [CRY_32X25_4]  150.5 50.8 270 top
Y2  25MHz  [CRY_32X25_4]  128.27 51.43 270 top
Y4  25MHz  [CRY_32X25_4]  235.46 130.17 0 top
Y5  25MHz  [CRY_32X25_4]  155.07 60.45 0 top
Y6  32.768KHz  [CRY_69X14_4]  100.33 86.36 270 top
Y7  50MHz  [CRY_32X25_4]  176.02 45.09 270 top
Y8  50MHz  [CRY_32X25_4]  226.82 45.09 270 top
Z97  -  [FIDUCIAL]  274.7 18.16 0 top
Z98  -  [FIDUCIAL]  11.81 239.14 0 top
Z99  -  [FIDUCIAL]  10.54 22.61 0 top
Z100  -  [FIDUCIAL]  268.99 240.41 0 top
Z101  -  [FIDUCIAL]  274.7 18.16 180 bottom
Z102  -  [FIDUCIAL]  11.81 239.14 180 bottom
Z103  -  [FIDUCIAL]  268.99 240.41 180 bottom
Z104  -  [FIDUCIAL]  10.54 22.61 180 bottom
Z105  MH_M8  [MH_900C400N_M]  141.02 245.02 0 top
Z106  MH_M8  [MH_900C400N_M]  275.02 245.02 0 top
Z107  MH_M8  [MH_900C400N_M]  127.02 11.02 0 top
Z108  MH_M8  [MH_900C400N_M]  275.02 11.02 0 top
Z109  MH_M8  [MH_900C400N_M]  7.02 16.02 0 top
Z110  MH_M8  [MH_900C400N_M]  7.02 245.02 0 top
Z111  MH_M8  [MH_900C400N_M]  34.04 133.73 0 top
Z112  MH_M8  [MH_900C400N_M]  220.73 84.84 0 top

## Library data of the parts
C1 C2 C15 C885 C886 C925 C926 C930 C931 C952-C955 C975 C976 C979 C980 C1112 C1113 C1208-C1210 C1228 C1229 C1233 C1234 = CAP: signal model: DEFAULT_CAPACITOR_2.2e+07pF_2_1
C3-C14 C16-C21 C23-C26 C30-C32 C34 C35 C37 C39 C48-C54 C57-C60 C67 C68 C84 C93 C94 C131 C133 C136 C147 C148 C150-C159 C170 C171 C176 C177 C179 C180 C182-C185 C192 C196-C208 C210-C220 C222 C232 C245-C248 C252-C255 C271-C275 C284-C288 C293 C295 C297 C313-C317 C319-C323 C325 C326 C329 C336 C344 C346-C351 C353-C355 C357 C358 C598 C599 C602-C607 C611-C614 C622-C625 C627-C631 C699-C701 C704 C706-C710 C712-C716 C720 C723 C729 C732 C735 C742 C743 C746 C747 C883 C891 C893-C898 C916-C919 C933 C935 C940 C941 C961 C963-C965 C984 C987-C989 C998 C999 C1002 C1011 C1012 C1022 C1026-C1036 C1044-C1048 C1050-C1052 C1079 C1081 C1101-C1105 C1114 C1115 C1117 C1118 C1164 C1165 C1179 C1186-C1190 C1197 C1214 C1222 C1223 C1236 C1238 C1239 C1243 C1254-C1261 C1265-C1270 C1274-C1277 C1280 C1283-C1286 C1333 C1334 C1347 C1354-C1358 C1365 C1378-C1393 = CAP: signal model: DEFAULT_CAPACITOR_100000pF_2_1
C22 C85 C134 C139 C163-C169 C223-C230 C296 C298 C299 C301 C310 C328 C330 C332 C333 C342 C702 C721 C730 C737 C751 C873-C876 C920-C923 C932 C938 C945 C947 C956 C957 C969 C971 C977 C981 C993 C995 C996 C1003-C1010 C1023 C1024 C1037-C1039 C1041 C1160-C1163 C1177 C1178 C1212 C1221 C1231 C1235 C1247 C1251 C1273 C1281 C1328 C1329 C1331 C1332 C1345 C1346 C1375-C1377 = CAP: signal model: DEFAULT_CAPACITOR_10000pF_2_1
C33 C36 C38 C135 C238-C241 C258 C268 C270 C698 C703 C705 C711 C722 C731 C884 C912-C915 C928 C929 C944 C946 C950 C951 C968 C970 C972-C974 C978 C992 C994 C1015 C1016 C1053-C1058 C1121 C1211 C1213 C1220 C1225-C1227 C1230 C1232 C1246 C1250 C1264 C1289 = CAP: signal model: DEFAULT_CAPACITOR_1e+06pF_2_1
C55 C56 C132 C300 C303 C331 C335 C718 C728 = CAP: signal model: DEFAULT_CAPACITOR_10.000000pF_2_1
C92 C125 C128 C130 C137 C140-C146 C175 C178 C181 C186-C189 C195 C209 C234-C237 C257 C267 C269 C600 C601 C609 C610 C621 C626 C736 C750 C880 C881 C890 C904-C911 C1017 C1040 C1049 C1116 C1263 C1278 C1279 = CAP: signal model: DEFAULT_CAPACITOR_1e+07pF_2_1
C124 C127 C620 = CAP_E: signal model: DEFAULT_CAPACITOR_1e+08pF_2_1
C126 C129 C294 C302 C309 C334 C341 C887 C1205 C1206 C1373 C1374 = CAP: signal model: DEFAULT_CAPACITOR_1000pF_2_1
C138 C149 C161 C162 C173 C174 C242 C243 C249 C250 C1122 C1123 C1125-C1129 C1131-C1141 C1143 C1144 C1146 C1148-C1152 C1154-C1159 C1166 C1169-C1176 C1181-C1183 C1191 C1193 C1198 C1199 C1201 C1202 C1204 C1290 C1291 C1294-C1297 C1299-C1301 C1303-C1319 C1322-C1327 C1330 C1337-C1344 C1349-C1351 C1359 C1361 C1366 C1367 C1369 C1370 C1372 = CAP: signal model: DEFAULT_CAPACITOR_2.2e+06pF_2_1
C160 C172 C244 C251 C259 C264 C1262 = CAP: signal model: DEFAULT_CAPACITOR_3000pF_2_1
C260 C265 C312 C324 C343 C356 C882 C1282 = CAP: signal model: DEFAULT_CAPACITOR_4.7e+06pF_2_1
C261 C266 C934 C936 C937 C939 C958-C960 C962 C982 C983 C985 C986 C1063 C1064 C1066-C1070 C1095-C1100 C1145 C1153 C1184 C1192 C1194 C1217 C1218 C1237 C1240-C1242 C1248 C1249 C1252 C1253 C1302 C1320 C1352 C1360 C1362 = CAP: signal model: DEFAULT_CAPACITOR_4.7e+07pF_2_1
C276-C279 C289-C292 = CAP: signal model: DEFAULT_CAPACITOR_100.000000pF_2_1
C304 C305 C339 C340 C739 = CAP: signal model: DEFAULT_CAPACITOR_27.000000pF_2_1
C307 C308 C337 C338 C1200 C1203 C1368 C1371 = CAP: signal model: DEFAULT_CAPACITOR_470.000000pF_2_1
C733 C734 = CAP: signal model: DEFAULT_CAPACITOR_2.000000pF_2_1
C738 = CAP: signal model: DEFAULT_CAPACITOR_33.000000pF_2_1
C892 = CAP: signal model: DEFAULT_CAPACITOR_22.000000pF_2_1
C924 C1207 = CAP: signal model: DEFAULT_CAPACITOR_330000pF_2_1
C927 C948 C949 C1224 = CAP: signal model: DEFAULT_CAPACITOR_470000pF_2_1
C942 C1219 = CAP: signal model: DEFAULT_CAPACITOR_510.000000pF_2_1
C943 C966 C1244 = CAP: signal model: DEFAULT_CAPACITOR_560.000000pF_2_1
C967 = CAP: signal model: DEFAULT_CAPACITOR_620.000000pF_2_1
C990 C991 C1245 = CAP: signal model: DEFAULT_CAPACITOR_680.000000pF_2_1
C1013 C1014 = CAP_3T_4P
C1080 = CAP_E: signal model: DEFAULT_CAPACITOR_2.2e+08pF_2_1
C1119 C1120 C1287 C1288 = CAP: signal model: DEFAULT_CAPACITOR_18.000000pF_2_1
C1124 C1130 C1142 C1147 C1167 C1168 C1180 C1185 C1292 C1293 C1298 C1321 C1335 C1336 C1348 C1353 = CAP: signal model: DEFAULT_CAPACITOR_1e+08pF_2_1
C1215 C1216 = CAP_E: signal model: DEFAULT_CAPACITOR_4.7e+08pF_2_1
D1 D43 D44 = LED
D3 D4 = DIODE
D33-D35 = DIODE_SCHOTTKY
F9-F15 = PTC
FB6-FB13 FB18-FB26 FB29 FB47 FB48 FB50 FB52 FB54-FB71 = BEAD
J1 = DDR3_DIMM
J2 = SD_CONN
J3 = CONN_2X8
J9-J11 = JMP2
J13 = RJ45_2X1
J14 = RJ45_LED_2X1
J18 = PCIE_X1
J19 J20 = MINIPCIE_CONN
J26 = CONN_2X5
J33 J34 J44-J46 J58 J59 = CONN_3PIN
J35 J47 J48 J61 = CONN_1X2
J37 = ATX_PWR_CONN_20PIN
J41 = USB_A_2
J43 = CONN_2X20
J49 = BAT_SOCKET
J50 J56 = RJ45_XG_LED
J51 J55 = CONN_1X7
J52-J54 J60 = CONN_1X3
J57 = CONN_1X1
L1 L2 = IND_CM
L3 L4 L17 L18 L22 L24 = IND_IRON: signal model: DEFAULT_INDUCTOR_2200nH_2_1
L16 = IND_IRON: signal model: DEFAULT_INDUCTOR_22000nH_2_1
L19 L20 = IND_IRON: signal model: DEFAULT_INDUCTOR_3300nH_2_1
L21 L25 = IND_IRON: signal model: DEFAULT_INDUCTOR_4700nH_2_1
L23 = IND_IRON: signal model: DEFAULT_INDUCTOR_1000nH_2_1
M3-M18 = MH
Q1-Q4 Q15 Q16 Q20 Q21 Q27-Q29 Q32-Q38 Q44 Q45 Q47-Q49 = NMOS
Q11 Q17 Q18 Q31 Q46 = NMOS_SO8FL
Q12 = PMOS_SO8
Q30 = TRANS_NPN
Q50 = TRANS_PNP
R1 R3 = RES: tolerance: 1%; signal model: DEFAULT_RESISTOR_162.000000OHM_2_1
R2 R83 R84 R138 R161 R162 R176 R494 R503 R505 R507 R509 R513 R518 R656 R666 R670 R672 R673 R681 R682 R713 R782 R785 R815 R820 R829 R830 R834 R842-R844 R883 R909 R919 R948 R950 R953 R954 R975 = RES: tolerance: 5%; signal model: DEFAULT_RESISTOR_1000.000000OHM_2_1
R4-R7 R9-R11 R13 R17 R19 R21 R23 R25 R27 R29 R31 R33-R44 R47 R54-R57 R69-R74 R81 R82 R85-R91 R94-R99 R101 R102 R123 R124 R132 R204 R228-R235 R252 R257-R264 R398-R411 R496 R499-R501 R705 R706 R708 R710 R712 R813 R823 R849-R853 R870-R872 R875-R879 R881 R884 R886 R895 R897 R940-R943 R952 R955 R957 R958 R965 R966 R968 R970 R976 R979 = RES: tolerance: 5%; signal model: DEFAULT_RESISTOR_4700OHM_2_1
R12 R59 R108 R115-R122 R125-R130 R549 R694 R839 R841 R981 R982 = RES: tolerance: 5%; signal model: DEFAULT_RESISTOR_10.000000OHM_2_1
R14-R16 R18 R20 R22 R24 R26 R28 R30 R32 R58 R175 R209 R211 R213-R217 R238 R239 R242-R246 R495 R511 R517 R868 = RES: tolerance: 5%; signal model: DEFAULT_RESISTOR_33.000000OHM_2_1
R60 R62-R68 R106 R107 R109-R114 R155 R156 R158 R159 R497 R498 R502 R504 R506 R508 R662 R663 R669 R671 R678 R679 R684 R685 R703 R704 R732 R734 R737 R739-R741 R750 R752 R754 R756 R758 R759 R768 R770 R771 R773 R776 R777 R784 R786 R818 R819 R821 R831 R906 R908 R910 R916 R920 R925 R927 R931-R934 R947 R949 = RES: tolerance: 5%; signal model: DEFAULT_RESISTOR_10000OHM_2_1
R61 R157 R160 R167-R170 R190 R193 R221 R222 R250 R251 R520 R521 R525 R526 R530 R532 R536 R537 R659 R675 R676 R700 R701 R742 R743 R760 R761 R778 R779 R783 R816 R817 R822 R824-R826 R836 R837 R861-R863 R873 R874 R880 R882 R885 R887-R892 R898-R900 R911 R912 R918 R935 R936 R945 R946 R959-R964 R967 R971-R973 R983-R987 R1012 R1015 = RES: tolerance: 5%; signal model: DEFAULT_RESISTOR_0.001OHM_2_1
R103 R133 R218 R219 R247 R248 R699 R702 = RES: tolerance: 5%; signal model: DEFAULT_RESISTOR_510.000000OHM_2_1
R104 R105 R140 = RES: tolerance: 1%; signal model: DEFAULT_RESISTOR_698.000000OHM_2_1
R131 = RES: tolerance: 5%; signal model: DEFAULT_RESISTOR_1500OHM_2_1
R134 = RES: tolerance: 5%; signal model: DEFAULT_RESISTOR_270.000000OHM_2_1
R139 = RES: tolerance: 1%; signal model: DEFAULT_RESISTOR_200.000000OHM_2_1
R163 R164 = RES: tolerance: 1%; signal model: DEFAULT_RESISTOR_51100OHM_2_1
R165 R166 = RES: tolerance: 1%; signal model: DEFAULT_RESISTOR_18200OHM_2_1
R171 R729 R731 R736 R738 R744 R748 R749 R753 R757 R766 R767 R772 R774 R807 R907 R913 R914 R922 R924 R929 R937 = RES: tolerance: 1%; signal model: DEFAULT_RESISTOR_10000OHM_2_1
R172 R173 R519 R523 R524 R527 R528 R534 R535 R538 R814 R835 R838 R1013 R1014 = RES: tolerance: 1%; signal model: DEFAULT_RESISTOR_49.900000OHM_2_1
R177-R179 = RES: tolerance: 5%; signal model: DEFAULT_RESISTOR_330.000000OHM_2_1
R188 R194 R195 R939 = RES: tolerance: 5%; signal model: DEFAULT_RESISTOR_5.100000OHM_2_1
R189 R192 = RES: tolerance: 1%; signal model: DEFAULT_RESISTOR_0.33OHM_2_1
R196-R203 R205 R206 R220 R249 R707 R711 R896 R902 R903 R969 R977 R978 = RES: tolerance: 5%; signal model: DEFAULT_RESISTOR_100.000000OHM_2_1
R207 R208 R210 R212 R236 R237 R240 R241 = RES: tolerance: 5%; signal model: DEFAULT_RESISTOR_75.000000OHM_2_1
R224 = RES: tolerance: 5%; signal model: DEFAULT_RESISTOR_15.000000OHM_2_1
R227 R256 R780 R928 = RES: tolerance: 1%; signal model: DEFAULT_RESISTOR_2490OHM_2_1
R253 = RES: signal model: DEFAULT_RESISTOR_15.000000OHM_2_1
R541-R544 R993 R995 R997 R999-R1003 = RES: tolerance: 5%; signal model: DEFAULT_RESISTOR_150.000000OHM_2_1
R695 R696 = RES: tolerance: 1%; signal model: DEFAULT_RESISTOR_1000.000000OHM_2_1
R697 R714 R715 = RES: tolerance: 5%; signal model: DEFAULT_RESISTOR_100000OHM_2_1
R709 = RES: tolerance: 1%; signal model: DEFAULT_RESISTOR_3740OHM_2_1
R728 = RES: tolerance: 1%; signal model: DEFAULT_RESISTOR_169000OHM_2_1
R730 R904 = RES: tolerance: 1%; signal model: DEFAULT_RESISTOR_124000OHM_2_1
R733 R905 = RES: tolerance: 1%; signal model: DEFAULT_RESISTOR_1650OHM_2_1
R735 = RES: tolerance: 1%; signal model: DEFAULT_RESISTOR_2050OHM_2_1
R745 = RES: tolerance: 1%; signal model: DEFAULT_RESISTOR_5900OHM_2_1
R746 = RES: tolerance: 1%; signal model: DEFAULT_RESISTOR_187000OHM_2_1
R747 = RES: tolerance: 1%; signal model: DEFAULT_RESISTOR_226000OHM_2_1
R751 = RES: tolerance: 1%; signal model: DEFAULT_RESISTOR_2210OHM_2_1
R755 = RES: tolerance: 1%; signal model: DEFAULT_RESISTOR_2430OHM_2_1
R762 = RES: tolerance: 1%; signal model: DEFAULT_RESISTOR_4990OHM_2_1
R763 = RES: tolerance: 1%; signal model: DEFAULT_RESISTOR_3830OHM_2_1
R764 = RES: tolerance: 1%; signal model: DEFAULT_RESISTOR_309000OHM_2_1
R765 = RES: tolerance: 1%; signal model: DEFAULT_RESISTOR_412000OHM_2_1
R769 = RES: tolerance: 1%; signal model: DEFAULT_RESISTOR_2550OHM_2_1
R775 = RES: tolerance: 1%; signal model: DEFAULT_RESISTOR_2320OHM_2_1
R781 = RES: tolerance: 1%; signal model: DEFAULT_RESISTOR_1780OHM_2_1
R797-R804 R864 = RES: tolerance: 5%; signal model: DEFAULT_RESISTOR_20000OHM_2_1
R806 = RES: tolerance: 1%; signal model: DEFAULT_RESISTOR_4320OHM_2_1
R865-R867 R869 = RES: tolerance: 5%; signal model: DEFAULT_RESISTOR_51.000000OHM_2_1
R901 R974 = RES: tolerance: 1%; signal model: DEFAULT_RESISTOR_2000OHM_2_1
R915 = RES: tolerance: 5%; signal model: DEFAULT_RESISTOR_200.000000OHM_2_1
R917 = RES: tolerance: 1%; signal model: DEFAULT_RESISTOR_60.400000OHM_2_1
R921 = RES: tolerance: 1%; signal model: DEFAULT_RESISTOR_261000OHM_2_1
R923 = RES: tolerance: 1%; signal model: DEFAULT_RESISTOR_150000OHM_2_1
R926 = RES: tolerance: 1%; signal model: DEFAULT_RESISTOR_1870OHM_2_1
R930 = RES: tolerance: 1%; signal model: DEFAULT_RESISTOR_14000OHM_2_1
R938 = RES: tolerance: 1%; signal model: DEFAULT_RESISTOR_3090OHM_2_1
R951 = RES: tolerance: 1%; signal model: DEFAULT_RESISTOR_26700OHM_2_1
R980 = RES_PWR
R988-R992 R994 R996 R998 = RES: tolerance: 5%; signal model: DEFAULT_RESISTOR_82.000000OHM_2_1
R1004-R1011 = RES: tolerance: 5%; signal model: DEFAULT_RESISTOR_130.000000OHM_2_1
R1016 = RES: tolerance: 5%
SW1-SW3 = SWITCH_DIP_8
SW4 SW5 = SWITCH_2P2
T1 T2 = H5004
TP1 TP2 TP11-TP18 = TP
U1 = T1024
U2 = 74LVC16373
U4 = FLASH-NOR-64Mx16
U8-U10 = 74LVC1G86
U13 = FLASH-SERIAL-SO16
U15 = FLASH-SERIAL-SON
U19 = PCA9546A
U20 = TXBN0304RSV
U21 U22 = FXLP34P5X
U23 U24 = 74LVC1G66
U37 = MAX1558H
U38 U47 U48 U50 U51 = SRV05-4
U39 U41 = MAX3232
U43 = LCDA15C-8
U44 = EEPROM-I2C
U45 = ADT7461
U46 U49 = RTL8211E-VB
U65 = EPM570F256
U68 = ICS843002-01
U81 = TPS51200
U83 = MAX811S
U84 = 74LVC2G74
U85 = 74LVC1G14
U86-U91 U103 U105 U106 = IR3475
U93 U94 = RClamp0524J
U95 = MIC47100-MSOP8
U97 = IDT9FGV0641
U100 = DS1339U
U101 U108 = AQ2104
U102 U109 = FLASH-SERIAL-SO8
U104 = 74CBTLV1G125
U107 = FLASH-NAND-BGA
U110 = PI3PCIE3212
U111 = INA220
U112 U113 = ICS859S0212I
X1-X3 X5 = OSC
Y1 Y2 Y4 Y5 Y7 Y8 = CRYSTAL_4PIN
Y6 = CRYSTAL_32K
Z97-Z104 = FIDUCIAL
Z105-Z112 = MH_M8

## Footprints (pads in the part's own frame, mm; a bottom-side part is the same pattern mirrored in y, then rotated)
0201
  rect 0.35x0.35 smd: 1(-0.3,0) 2(0.3,0)
0402
  rect 0.55x0.55 smd: 1(-0.5,0) 2(0.5,0)
0402O
  custom 0.138x0.138 smd: 1(-0.5,0) 2(0.5,0)
0603
  rect 0.9x0.9 smd: 1(-0.8,0) 2(0.8,0)
0805
  rect 1x1.4 smd: 1(-1,0) 2(1,0)
1206
  rect 1.25x1.6 smd: 1(-1.5,0) 2(1.5,0)
7343
  rect 2.4x2.9 smd: 1(-3.05,0) 2(3.05,0)
BGA_P080_780
  round 0.35 smd: A2(-10,10.8) A3(-9.2,10.8) A4(-8.4,10.8) A5(-7.6,10.8) A6(-6.8,10.8) A7(-6,10.8) A8(-5.2,10.8) A9(-4.4,10.8) A10(-3.6,10.8) A11(-2.8,10.8) A12(-2,10.8) A13(-1.2,10.8) A14(-0.4,10.8) A15(0.4,10.8) A16(1.2,10.8) A17(2,10.8) A18(2.8,10.8) A19(3.6,10.8) A20(4.4,10.8) A21(5.2,10.8) A22(6,10.8) A23(6.8,10.8) A24(7.6,10.8) A25(8.4,10.8) A26(9.2,10.8) A27(10,10.8) AA1(-10.8,-5.2) AA2(-10,-5.2) AA3(-9.2,-5.2) AA4(-8.4,-5.2) AA5(-7.6,-5.2) AA6(-6.8,-5.2) AA7(-6,-5.2) AA8(-5.2,-5.2) AA9(-4.4,-5.2) AA10(-3.6,-5.2) AA11(-2.8,-5.2) AA12(-2,-5.2) AA13(-1.2,-5.2) AA14(-0.4,-5.2) AA15(0.4,-5.2) AA16(1.2,-5.2) AA17(2,-5.2) AA18(2.8,-5.2) AA19(3.6,-5.2) AA20(4.4,-5.2) AA21(5.2,-5.2) AA22(6,-5.2) AA23(6.8,-5.2) AA24(7.6,-5.2) AA25(8.4,-5.2) AA26(9.2,-5.2) AA27(10,-5.2) AA28(10.8,-5.2) AB1(-10.8,-6) AB2(-10,-6) AB3(-9.2,-6) AB4(-8.4,-6) AB5(-7.6,-6) AB6(-6.8,-6) AB7(-6,-6) AB8(-5.2,-6) AB9(-4.4,-6) AB10(-3.6,-6) AB11(-2.8,-6) AB12(-2,-6) AB13(-1.2,-6) AB14(-0.4,-6) AB15(0.4,-6) AB16(1.2,-6) AB17(2,-6) AB18(2.8,-6) AB19(3.6,-6) AB20(4.4,-6) AB21(5.2,-6) AB22(6,-6) AB23(6.8,-6) AB24(7.6,-6) AB25(8.4,-6) AB26(9.2,-6) AB27(10,-6) AB28(10.8,-6) AC1(-10.8,-6.8) AC2(-10,-6.8) AC3(-9.2,-6.8) AC4(-8.4,-6.8) AC5(-7.6,-6.8) AC6(-6.8,-6.8) AC7(-6,-6.8) AC8(-5.2,-6.8) AC9(-4.4,-6.8) AC10(-3.6,-6.8) AC11(-2.8,-6.8) AC12(-2,-6.8) AC13(-1.2,-6.8) AC14(-0.4,-6.8) AC15(0.4,-6.8) AC16(1.2,-6.8) AC17(2,-6.8) AC18(2.8,-6.8) AC19(3.6,-6.8) AC20(4.4,-6.8) AC21(5.2,-6.8) AC22(6,-6.8) AC23(6.8,-6.8) AC24(7.6,-6.8) AC25(8.4,-6.8) AC26(9.2,-6.8) AC27(10,-6.8) AC28(10.8,-6.8) AD1(-10.8,-7.6) AD2(-10,-7.6) AD3(-9.2,-7.6) AD4(-8.4,-7.6) AD5(-7.6,-7.6) AD6(-6.8,-7.6) AD7(-6,-7.6) AD8(-5.2,-7.6) AD9(-4.4,-7.6) AD10(-3.6,-7.6) AD11(-2.8,-7.6) AD12(-2,-7.6) AD13(-1.2,-7.6) AD14(-0.4,-7.6) AD15(0.4,-7.6) AD16(1.2,-7.6) AD17(2,-7.6) AD18(2.8,-7.6) AD19(3.6,-7.6) AD20(4.4,-7.6) AD21(5.2,-7.6) AD22(6,-7.6) AD23(6.8,-7.6) AD24(7.6,-7.6) AD25(8.4,-7.6) AD26(9.2,-7.6) AD27(10,-7.6) AD28(10.8,-7.6) AE1(-10.8,-8.4) AE2(-10,-8.4) AE3(-9.2,-8.4) AE4(-8.4,-8.4) AE5(-7.6,-8.4) AE6(-6.8,-8.4) AE7(-6,-8.4) AE8(-5.2,-8.4) AE9(-4.4,-8.4) AE10(-3.6,-8.4) AE11(-2.8,-8.4) AE12(-2,-8.4) AE13(-1.2,-8.4) AE14(-0.4,-8.4) AE15(0.4,-8.4) AE16(1.2,-8.4) AE17(2,-8.4) AE18(2.8,-8.4) AE19(3.6,-8.4) AE20(4.4,-8.4) AE21(5.2,-8.4) AE22(6,-8.4) AE23(6.8,-8.4) AE24(7.6,-8.4) AE25(8.4,-8.4) AE26(9.2,-8.4) AE27(10,-8.4) AE28(10.8,-8.4) AF1(-10.8,-9.2) AF2(-10,-9.2) AF3(-9.2,-9.2) AF4(-8.4,-9.2) AF5(-7.6,-9.2) AF6(-6.8,-9.2) AF7(-6,-9.2) AF8(-5.2,-9.2) AF9(-4.4,-9.2) AF10(-3.6,-9.2) AF11(-2.8,-9.2) AF12(-2,-9.2) AF13(-1.2,-9.2) AF14(-0.4,-9.2) AF15(0.4,-9.2) AF16(1.2,-9.2) AF17(2,-9.2) AF18(2.8,-9.2) AF19(3.6,-9.2) AF20(4.4,-9.2) AF21(5.2,-9.2) AF22(6,-9.2) AF23(6.8,-9.2) AF24(7.6,-9.2) AF25(8.4,-9.2) AF26(9.2,-9.2) AF27(10,-9.2) AF28(10.8,-9.2) AG1(-10.8,-10) AG2(-10,-10) AG3(-9.2,-10) AG4(-8.4,-10) AG5(-7.6,-10) AG6(-6.8,-10) AG7(-6,-10) AG8(-5.2,-10) AG9(-4.4,-10) AG10(-3.6,-10) AG11(-2.8,-10) AG12(-2,-10) AG13(-1.2,-10) AG14(-0.4,-10) AG15(0.4,-10) AG16(1.2,-10) AG17(2,-10) AG18(2.8,-10) AG19(3.6,-10) AG20(4.4,-10) AG21(5.2,-10) AG22(6,-10) AG23(6.8,-10) AG24(7.6,-10) AG25(8.4,-10) AG26(9.2,-10) AG27(10,-10) AG28(10.8,-10) AH2(-10,-10.8) AH3(-9.2,-10.8) AH4(-8.4,-10.8) AH5(-7.6,-10.8) AH6(-6.8,-10.8) AH7(-6,-10.8) AH8(-5.2,-10.8) AH9(-4.4,-10.8) AH10(-3.6,-10.8) AH11(-2.8,-10.8) AH12(-2,-10.8) AH13(-1.2,-10.8) AH14(-0.4,-10.8) AH15(0.4,-10.8) AH16(1.2,-10.8) AH17(2,-10.8) AH18(2.8,-10.8) AH19(3.6,-10.8) AH20(4.4,-10.8) AH21(5.2,-10.8) AH22(6,-10.8) AH23(6.8,-10.8) AH24(7.6,-10.8) AH25(8.4,-10.8) AH26(9.2,-10.8) AH27(10,-10.8) B1(-10.8,10) B2(-10,10) B3(-9.2,10) B4(-8.4,10) B5(-7.6,10) B6(-6.8,10) B7(-6,10) B8(-5.2,10) B9(-4.4,10) B10(-3.6,10) B11(-2.8,10) B12(-2,10) B13(-1.2,10) B14(-0.4,10) B15(0.4,10) B16(1.2,10) B17(2,10) B18(2.8,10) B19(3.6,10) B20(4.4,10) B21(5.2,10) B22(6,10) B23(6.8,10) B24(7.6,10) B25(8.4,10) B26(9.2,10) B27(10,10) B28(10.8,10) C1(-10.8,9.2) C2(-10,9.2) C3(-9.2,9.2) C4(-8.4,9.2) C5(-7.6,9.2) C6(-6.8,9.2) C7(-6,9.2) C8(-5.2,9.2) C9(-4.4,9.2) C10(-3.6,9.2) C11(-2.8,9.2) C12(-2,9.2) C13(-1.2,9.2) C14(-0.4,9.2) C15(0.4,9.2) C16(1.2,9.2) C17(2,9.2) C18(2.8,9.2) C19(3.6,9.2) C20(4.4,9.2) C21(5.2,9.2) C22(6,9.2) C23(6.8,9.2) C24(7.6,9.2) C25(8.4,9.2) C26(9.2,9.2) C27(10,9.2) C28(10.8,9.2) D1(-10.8,8.4) D2(-10,8.4) D3(-9.2,8.4) D4(-8.4,8.4) D5(-7.6,8.4) D6(-6.8,8.4) D7(-6,8.4) D8(-5.2,8.4) D9(-4.4,8.4) D10(-3.6,8.4) D11(-2.8,8.4) D12(-2,8.4) D13(-1.2,8.4) D14(-0.4,8.4) D15(0.4,8.4) D16(1.2,8.4) D17(2,8.4) D18(2.8,8.4) D19(3.6,8.4) D20(4.4,8.4) D21(5.2,8.4) D22(6,8.4) D23(6.8,8.4) D24(7.6,8.4) D25(8.4,8.4) D26(9.2,8.4) D27(10,8.4) D28(10.8,8.4) E1(-10.8,7.6) E2(-10,7.6) E3(-9.2,7.6) E4(-8.4,7.6) E5(-7.6,7.6) E6(-6.8,7.6) E7(-6,7.6) E8(-5.2,7.6) E9(-4.4,7.6) E10(-3.6,7.6) E11(-2.8,7.6) E12(-2,7.6) E13(-1.2,7.6) E14(-0.4,7.6) E15(0.4,7.6) E16(1.2,7.6) E17(2,7.6) E18(2.8,7.6) E19(3.6,7.6) E20(4.4,7.6) E21(5.2,7.6) E22(6,7.6) E23(6.8,7.6) E24(7.6,7.6) E25(8.4,7.6) E26(9.2,7.6) E27(10,7.6) E28(10.8,7.6) F1(-10.8,6.8) F2(-10,6.8) F3(-9.2,6.8) F4(-8.4,6.8) F5(-7.6,6.8) F6(-6.8,6.8) F7(-6,6.8) F8(-5.2,6.8) F9(-4.4,6.8) F10(-3.6,6.8) F11(-2.8,6.8) F12(-2,6.8) F13(-1.2,6.8) F14(-0.4,6.8) F15(0.4,6.8) F16(1.2,6.8) F17(2,6.8) F18(2.8,6.8) F19(3.6,6.8) F20(4.4,6.8) F21(5.2,6.8) F22(6,6.8) F23(6.8,6.8) F24(7.6,6.8) F25(8.4,6.8) F26(9.2,6.8) F27(10,6.8) F28(10.8,6.8) G1(-10.8,6) G2(-10,6) G3(-9.2,6) G4(-8.4,6) G5(-7.6,6) G6(-6.8,6) G7(-6,6) G8(-5.2,6) G9(-4.4,6) G10(-3.6,6) G11(-2.8,6) G12(-2,6) G13(-1.2,6) G14(-0.4,6) G15(0.4,6) G16(1.2,6) G17(2,6) G18(2.8,6) G19(3.6,6) G20(4.4,6) G21(5.2,6) G22(6,6) G23(6.8,6) G24(7.6,6) G25(8.4,6) G26(9.2,6) G27(10,6) G28(10.8,6) H1(-10.8,5.2) H2(-10,5.2) H3(-9.2,5.2) H4(-8.4,5.2) H5(-7.6,5.2) H6(-6.8,5.2) H7(-6,5.2) H8(-5.2,5.2) H9(-4.4,5.2) H10(-3.6,5.2) H11(-2.8,5.2) H12(-2,5.2) H13(-1.2,5.2) H14(-0.4,5.2) H15(0.4,5.2) H16(1.2,5.2) H17(2,5.2) H18(2.8,5.2) H19(3.6,5.2) H20(4.4,5.2) H21(5.2,5.2) H22(6,5.2) H23(6.8,5.2) H24(7.6,5.2) H25(8.4,5.2) H26(9.2,5.2) H27(10,5.2) H28(10.8,5.2) J1(-10.8,4.4) J2(-10,4.4) J3(-9.2,4.4) J4(-8.4,4.4) J5(-7.6,4.4) J6(-6.8,4.4) J7(-6,4.4) J8(-5.2,4.4) J9(-4.4,4.4) J10(-3.6,4.4) J11(-2.8,4.4) J12(-2,4.4) J13(-1.2,4.4) J14(-0.4,4.4) J15(0.4,4.4) J16(1.2,4.4) J17(2,4.4) J18(2.8,4.4) J19(3.6,4.4) J20(4.4,4.4) J21(5.2,4.4) J22(6,4.4) J23(6.8,4.4) J24(7.6,4.4) J25(8.4,4.4) J26(9.2,4.4) J27(10,4.4) J28(10.8,4.4) K1(-10.8,3.6) K2(-10,3.6) K3(-9.2,3.6) K4(-8.4,3.6) K5(-7.6,3.6) K6(-6.8,3.6) K7(-6,3.6) K8(-5.2,3.6) K9(-4.4,3.6) K10(-3.6,3.6) K11(-2.8,3.6) K12(-2,3.6) K13(-1.2,3.6) K14(-0.4,3.6) K15(0.4,3.6) K16(1.2,3.6) K17(2,3.6) K18(2.8,3.6) K19(3.6,3.6) K20(4.4,3.6) K21(5.2,3.6) K22(6,3.6) K23(6.8,3.6) K24(7.6,3.6) K25(8.4,3.6) K26(9.2,3.6) K27(10,3.6) K28(10.8,3.6) L1(-10.8,2.8) L2(-10,2.8) L3(-9.2,2.8) L4(-8.4,2.8) L5(-7.6,2.8) L6(-6.8,2.8) L7(-6,2.8) L8(-5.2,2.8) L9(-4.4,2.8) L10(-3.6,2.8) L11(-2.8,2.8) L12(-2,2.8) L13(-1.2,2.8) L14(-0.4,2.8) L15(0.4,2.8) L16(1.2,2.8) L17(2,2.8) L18(2.8,2.8) L19(3.6,2.8) L20(4.4,2.8) L21(5.2,2.8) L22(6,2.8) L23(6.8,2.8) L24(7.6,2.8) L25(8.4,2.8) L26(9.2,2.8) L27(10,2.8) L28(10.8,2.8) M1(-10.8,2) M2(-10,2) M3(-9.2,2) M4(-8.4,2) M5(-7.6,2) M6(-6.8,2) M7(-6,2) M8(-5.2,2) M9(-4.4,2) M10(-3.6,2) M11(-2.8,2) M12(-2,2) M13(-1.2,2) M14(-0.4,2) M15(0.4,2) M16(1.2,2) M17(2,2) M18(2.8,2) M19(3.6,2) M20(4.4,2) M21(5.2,2) M22(6,2) M23(6.8,2) M24(7.6,2) M25(8.4,2) M26(9.2,2) M27(10,2) M28(10.8,2) N1(-10.8,1.2) N2(-10,1.2) N3(-9.2,1.2) N4(-8.4,1.2) N5(-7.6,1.2) N6(-6.8,1.2) N7(-6,1.2) N8(-5.2,1.2) N9(-4.4,1.2) N10(-3.6,1.2) N11(-2.8,1.2) N12(-2,1.2) N13(-1.2,1.2) N14(-0.4,1.2) N15(0.4,1.2) N16(1.2,1.2) N17(2,1.2) N18(2.8,1.2) N19(3.6,1.2) N20(4.4,1.2) N21(5.2,1.2) N22(6,1.2) N23(6.8,1.2) N24(7.6,1.2) N25(8.4,1.2) N26(9.2,1.2) N27(10,1.2) N28(10.8,1.2) P1(-10.8,0.4) P2(-10,0.4) P3(-9.2,0.4) P4(-8.4,0.4) P5(-7.6,0.4) P6(-6.8,0.4) P7(-6,0.4) P8(-5.2,0.4) P9(-4.4,0.4) P10(-3.6,0.4) P11(-2.8,0.4) P12(-2,0.4) P13(-1.2,0.4) P14(-0.4,0.4) P15(0.4,0.4) P16(1.2,0.4) P17(2,0.4) P18(2.8,0.4) P19(3.6,0.4) P20(4.4,0.4) P21(5.2,0.4) P22(6,0.4) P23(6.8,0.4) P24(7.6,0.4) P25(8.4,0.4) P26(9.2,0.4) P27(10,0.4) P28(10.8,0.4) R1(-10.8,-0.4) R2(-10,-0.4) R3(-9.2,-0.4) R4(-8.4,-0.4) R5(-7.6,-0.4) R6(-6.8,-0.4) R7(-6,-0.4) R8(-5.2,-0.4) R9(-4.4,-0.4) R10(-3.6,-0.4) R11(-2.8,-0.4) R12(-2,-0.4) R13(-1.2,-0.4) R14(-0.4,-0.4) R15(0.4,-0.4) R16(1.2,-0.4) R17(2,-0.4) R18(2.8,-0.4) R19(3.6,-0.4) R20(4.4,-0.4) R21(5.2,-0.4) R22(6,-0.4) R23(6.8,-0.4) R24(7.6,-0.4) R25(8.4,-0.4) R26(9.2,-0.4) R27(10,-0.4) R28(10.8,-0.4) T1(-10.8,-1.2) T2(-10,-1.2) T3(-9.2,-1.2) T4(-8.4,-1.2) T5(-7.6,-1.2) T6(-6.8,-1.2) T7(-6,-1.2) T8(-5.2,-1.2) T9(-4.4,-1.2) T10(-3.6,-1.2) T11(-2.8,-1.2) T12(-2,-1.2) T13(-1.2,-1.2) T14(-0.4,-1.2) T15(0.4,-1.2) T16(1.2,-1.2) T17(2,-1.2) T18(2.8,-1.2) T19(3.6,-1.2) T20(4.4,-1.2) T21(5.2,-1.2) T22(6,-1.2) T23(6.8,-1.2) T24(7.6,-1.2) T25(8.4,-1.2) T26(9.2,-1.2) T27(10,-1.2) T28(10.8,-1.2) U1(-10.8,-2) U2(-10,-2) U3(-9.2,-2) U4(-8.4,-2) U5(-7.6,-2) U6(-6.8,-2) U7(-6,-2) U8(-5.2,-2) U9(-4.4,-2) U10(-3.6,-2) U11(-2.8,-2) U12(-2,-2) U13(-1.2,-2) U14(-0.4,-2) U15(0.4,-2) U16(1.2,-2) U17(2,-2) U18(2.8,-2) U19(3.6,-2) U20(4.4,-2) U21(5.2,-2) U22(6,-2) U23(6.8,-2) U24(7.6,-2) U25(8.4,-2) U26(9.2,-2) U27(10,-2) U28(10.8,-2) V1(-10.8,-2.8) V2(-10,-2.8) V3(-9.2,-2.8) V4(-8.4,-2.8) V5(-7.6,-2.8) V6(-6.8,-2.8) V7(-6,-2.8) V8(-5.2,-2.8) V9(-4.4,-2.8) V10(-3.6,-2.8) V11(-2.8,-2.8) V12(-2,-2.8) V13(-1.2,-2.8) V14(-0.4,-2.8) V15(0.4,-2.8) V16(1.2,-2.8) V17(2,-2.8) V18(2.8,-2.8) V19(3.6,-2.8) V20(4.4,-2.8) V21(5.2,-2.8) V22(6,-2.8) V23(6.8,-2.8) V24(7.6,-2.8) V25(8.4,-2.8) V26(9.2,-2.8) V27(10,-2.8) V28(10.8,-2.8) W1(-10.8,-3.6) W2(-10,-3.6) W3(-9.2,-3.6) W4(-8.4,-3.6) W5(-7.6,-3.6) W6(-6.8,-3.6) W7(-6,-3.6) W8(-5.2,-3.6) W9(-4.4,-3.6) W10(-3.6,-3.6) W11(-2.8,-3.6) W12(-2,-3.6) W13(-1.2,-3.6) W14(-0.4,-3.6) W15(0.4,-3.6) W16(1.2,-3.6) W17(2,-3.6) W18(2.8,-3.6) W19(3.6,-3.6) W20(4.4,-3.6) W21(5.2,-3.6) W22(6,-3.6) W23(6.8,-3.6) W24(7.6,-3.6) W25(8.4,-3.6) W26(9.2,-3.6) W27(10,-3.6) W28(10.8,-3.6) Y1(-10.8,-4.4) Y2(-10,-4.4) Y3(-9.2,-4.4) Y4(-8.4,-4.4) Y5(-7.6,-4.4) Y6(-6.8,-4.4) Y7(-6,-4.4) Y8(-5.2,-4.4) Y9(-4.4,-4.4) Y10(-3.6,-4.4) Y11(-2.8,-4.4) Y12(-2,-4.4) Y13(-1.2,-4.4) Y14(-0.4,-4.4) Y15(0.4,-4.4) Y16(1.2,-4.4) Y17(2,-4.4) Y18(2.8,-4.4) Y19(3.6,-4.4) Y20(4.4,-4.4) Y21(5.2,-4.4) Y22(6,-4.4) Y23(6.8,-4.4) Y24(7.6,-4.4) Y25(8.4,-4.4) Y26(9.2,-4.4) Y27(10,-4.4) Y28(10.8,-4.4)
